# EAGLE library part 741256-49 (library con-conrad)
Connector with Kabel
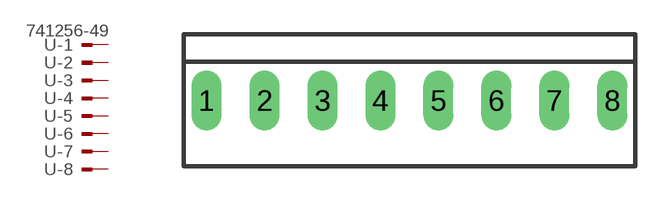
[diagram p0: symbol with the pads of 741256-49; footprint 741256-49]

Designator prefix -; gates -1=PIN-NV -2=PIN-N -3=PIN-N -4=PIN-N -5=PIN-N -6=PIN-N -7=PIN-N -8=PIN-N

## 741256-49  [741256-49]
1  -1:KL  pas
2  -2:KL  pas
3  -3:KL  pas
4  -4:KL  pas
5  -5:KL  pas
6  -6:KL  pas
7  -7:KL  pas
8  -8:KL  pas

## Footprint 741256-49 (pad centres in mm)
Pin connector 741256-49 vertikal
drill 0.813 pad 1.27 long: 1 -8.89,0; 2 -6.35,0; 3 -3.81,0; 4 -1.27,0; 5 1.27,0; 6 3.81,0; 7 6.35,0; 8 8.89,0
